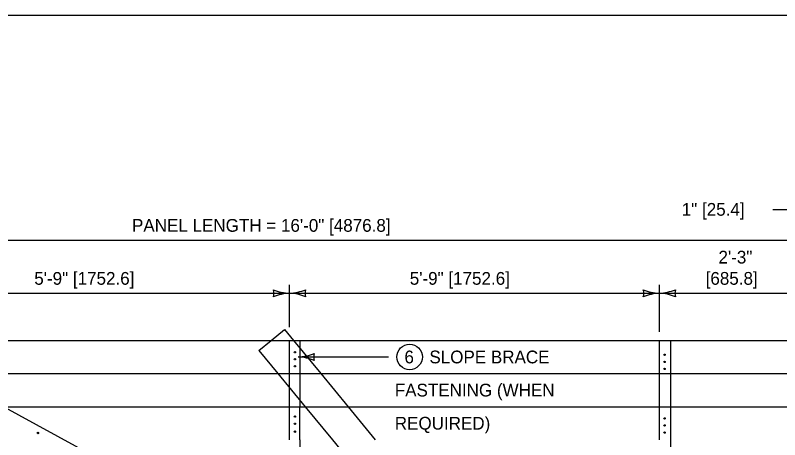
# Model space of a CAD drawing. Extents: x 49991 to 79985, y 47703 to 60542.
# Drawn here: x 50002.281 to 50005.885, y 49997.001 to 49998.999 of the extents above; entities that cross this region are included whole.
import ezdxf

# ---------------------------------------------------------------- set-up
doc = ezdxf.new("R2010")
doc.units = 0
for name, color, linetype in [('Level 1', 7, 'Continuous'), ('Level 2', 7, 'Continuous'), ('Level 3', 7, 'Continuous'), ('Level 4', 7, 'Continuous')]:
    doc.layers.add(name, color=color, linetype=linetype)

msp = doc.modelspace()

# ---------------------------------------------------------------- linework, layer by layer
at = {"layer": 'Level 1'}
for p, q in [((50005.8334, 49995.1946), (50001.4473, 49997.5783)), ((50003.4871, 49997.4683), (50003.5503, 49997.5204)), ((50003.5503, 49997.5204), (50003.5933, 49997.4683)), ((50001.6497, 49997.4683), (50006.0718, 49997.4683)), ((50001.9368, 49997.3123), (50006.0719, 49997.3123)), ((50003.5196, 49997.3123), (50003.6481, 49997.1563)), ((50003.7218, 49997.3123), (50003.8503, 49997.1563)), ((50005.3179, 49997.1563), (50005.3179, 49997.3123)), ((50005.3699, 49997.3123), (50005.3699, 49997.1563)), ((50003.5742, 49997.1563), (50003.5742, 49997.246)), ((50003.6236, 49997.186), (50003.6236, 49997.1563)), ((50002.2238, 49997.1563), (50006.0719, 49997.1563)), ((50003.6236, 49997.0008), (50003.6236, 49996.8443)), ((50003.7762, 49997.0008), (50003.9051, 49996.8443)), ((50005.3699, 49997.0008), (50005.3699, 49996.8443))]:
    msp.add_line(p, q, dxfattribs=at)
msp.add_lwpolyline([(49999.3835, 49998.9992), (50016.7501, 49998.9992), (50016.7501, 49987.7988), (49999.3835, 49987.7988)], close=True, dxfattribs=at)
for centre in [(50003.5997, 49997.4129), (50003.5997, 49997.3797), (50005.3426, 49997.4005), (50003.5997, 49997.3464), (50005.3426, 49997.3672), (50005.3426, 49997.3339), (50003.5997, 49997.1094), (50005.3426, 49997.1011), (50003.5997, 49997.0761), (50005.3426, 49997.0678), (50002.388, 49997.0324), (50003.5997, 49997.0387), (50005.3426, 49997.0345)]:
    msp.add_circle(centre, 0.00327, dxfattribs=at)
at = {"layer": 'Level 2'}
msp.add_circle((50004.1405, 49997.3903), 0.06, dxfattribs=at)
at = {"layer": 'Level 3'}
for p, q in [((50005.852, 49998.0854), (50006.0719, 49998.0854)), ((50001.0799, 49997.9399), (50006.0719, 49997.9399)), ((50003.5742, 49997.5314), (50003.5742, 49997.7304)), ((50005.3179, 49997.5083), (50005.3179, 49997.7304)), ((50001.7802, 49997.6904), (50003.5742, 49997.6904)), ((50003.5742, 49997.6904), (50005.3205, 49997.6904)), ((50005.3179, 49997.6904), (50006.0719, 49997.6904)), ((50003.6151, 49997.3903), (50004.0405, 49997.3903))]:
    msp.add_line(p, q, dxfattribs=at)
for centre, radius, start, end in [((50003.5834, 49997.9125), 0.2223, 247.456, 267.6395), ((50003.446, 49997.6904), 0.0548, 342.1388, 17.8612), ((50003.5627, 49997.9231), 0.233, 272.8273, 292.0772), ((50003.7024, 49997.6904), 0.0548, 162.1388, 197.8612), ((50005.3271, 49997.9125), 0.2223, 247.456, 267.6395), ((50005.1897, 49997.6904), 0.0548, 342.1388, 17.8612), ((50005.3064, 49997.9231), 0.233, 272.8273, 292.0772), ((50005.4461, 49997.6904), 0.0548, 162.1388, 197.8612), ((50003.5857, 49997.4577), 0.233, 92.8273, 112.0772), ((50003.565, 49997.4683), 0.2223, 67.456, 87.6395), ((50005.3294, 49997.4577), 0.233, 92.8273, 112.0772), ((50005.3087, 49997.4683), 0.2223, 67.456, 87.6395), ((50003.6036, 49997.623), 0.233, 272.8273, 292.0772), ((50003.6059, 49997.1682), 0.2223, 67.456, 87.6395), ((50003.7433, 49997.3903), 0.0548, 162.1388, 197.8612)]:
    msp.add_arc(centre, radius, start, end, dxfattribs=at)
at = {"layer": 'Level 4'}
for p, q in [((50003.4299, 49997.4213), (50003.4871, 49997.4683)), ((50003.5742, 49997.246), (50003.5742, 49997.4683)), ((50003.5933, 49997.4683), (50003.7218, 49997.3123)), ((50003.6236, 49997.4683), (50003.6236, 49997.186)), ((50005.3179, 49997.3123), (50005.3179, 49997.4683)), ((50005.3699, 49997.4683), (50005.3699, 49997.3123)), ((50003.4299, 49997.4213), (50003.5196, 49997.3123)), ((50003.5742, 49997.0008), (50003.5742, 49997.1563)), ((50003.6236, 49997.0008), (50003.6236, 49997.1563)), ((50003.6481, 49997.1563), (50003.7762, 49997.0008)), ((50003.8503, 49997.1563), (50003.9783, 49997.0008)), ((50005.3179, 49997.0008), (50005.3179, 49997.1563)), ((50005.3699, 49997.1563), (50005.3699, 49997.0008))]:
    msp.add_line(p, q, dxfattribs=at)

# ---------------------------------------------------------------- texts
at = {"layer": 'Level 2'}
for s, p in [('1" [25.4]', (50005.4234, 49998.0554)), ('PANEL LENGTH = 16\'-0" [4876.8]', (50002.8316, 49997.9799)), ('2\'-3"', (50005.5964, 49997.8304)), ('5\'-9" [1752.6]', (50002.3709, 49997.7304)), ('5\'-9" [1752.6]', (50004.1411, 49997.7304)), ('[685.8]', (50005.5359, 49997.7304)), ('6', (50004.116, 49997.3603)), ('SLOPE BRACE ', (50004.2336, 49997.3603)), ('FASTENING (WHEN', (50004.0705, 49997.2043)), ('REQUIRED)', (50004.0705, 49997.0483))]:
    msp.add_text(s, height=0.06, dxfattribs=at).set_placement(p)

doc.saveas('drawing.dxf')
